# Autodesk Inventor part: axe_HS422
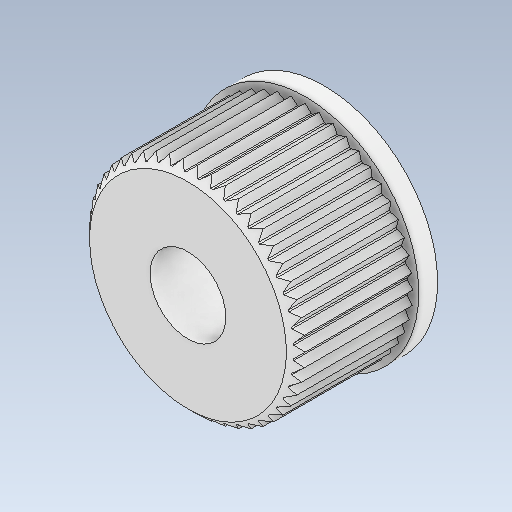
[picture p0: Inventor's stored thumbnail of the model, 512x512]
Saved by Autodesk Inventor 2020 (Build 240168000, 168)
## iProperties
Created: 2012-04
Part Number: axe_HS422
Material: Générique
Document SubType Name: Modeling
Designer: bruno
Density: 1 g/cm^3
Appearance: Par défaut
Author: bruno
Sending System: SolidWorks 2016
Last Author: Prof
Last Saved: 2018-11-12
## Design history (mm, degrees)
feature "Enlèvement de matière-Révolution1"
node "Solide1"
